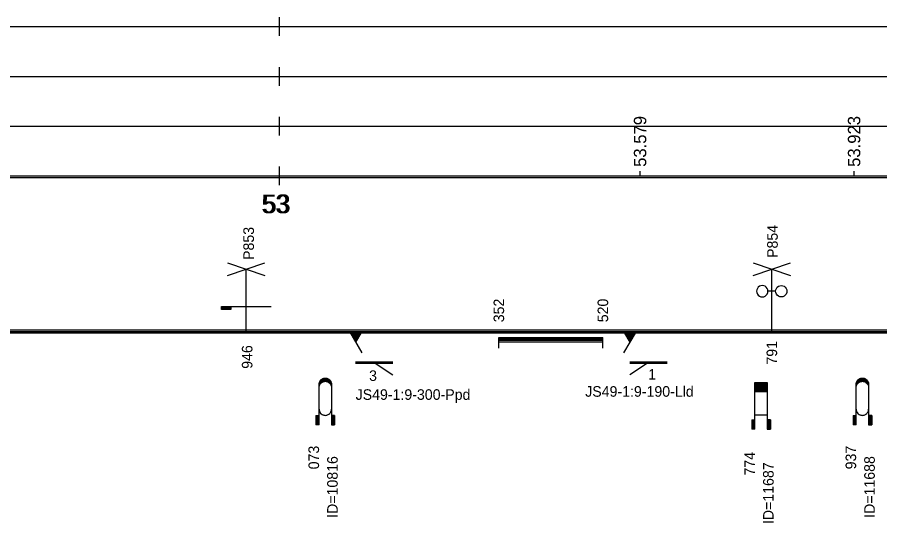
# Model space of a CAD drawing. Extents: x 2 to 10148, y 0 to 380.
# Drawn here: x 5559.3 to 5697.9, y 94.2 to 175.5 of the extents above; entities that cross this region are included whole.
import ezdxf

# ---------------------------------------------------------------- set-up
doc = ezdxf.new("R2010")
doc.units = 0
for name, color, linetype in [('CARA_S_OBJEKTY', 7, 'Continuous'), ('L_OBJEKTY_TEXT', 7, 'Continuous'), ('L_OBJEKTY_TVAR', 7, 'Continuous'), ('OBJEKTY_TEXT', 7, 'Continuous'), ('OBJEKTY_TVAR', 7, 'Continuous'), ('RYCHL_RASTR', 7, 'Continuous'), ('RYCHL_STAN', 7, 'Continuous'), ('STANIC_ZMEN_V', 7, 'Continuous')]:
    doc.layers.add(name, color=color, linetype=linetype)

msp = doc.modelspace()

# ---------------------------------------------------------------- linework, layer by layer
at = {"layer": 'CARA_S_OBJEKTY'}
for p, q in [((5128.6, 125.25), (5974.91, 125.25)), ((5128.6, 125), (5974.91, 125)), ((5128.6, 124.75), (5974.91, 124.75))]:
    msp.add_line(p, q, dxfattribs=at)
at = {"layer": 'L_OBJEKTY_TVAR'}
for p, q in [((5636.72, 124), (5653.44, 124)), ((5636.72, 122.33), (5636.72, 124)), ((5636.72, 123.83), (5653.44, 123.83)), ((5636.72, 123.58), (5653.44, 123.58)), ((5653.44, 122.33), (5653.44, 124)), ((5636.72, 123.33), (5653.44, 123.33))]:
    msp.add_line(p, q, dxfattribs=at)
at = {"layer": 'OBJEKTY_TVAR'}
for p, q in [((5593.12, 134), (5599.12, 136)), ((5593.12, 136), (5599.12, 134)), ((5677.59, 134), (5683.59, 136)), ((5677.59, 136), (5683.59, 134)), ((5596.12, 125), (5596.12, 135)), ((5680.59, 125), (5680.59, 135)), ((5678.27, 131.92), (5678.18, 131.7)), ((5678.42, 132.11), (5678.27, 131.92)), ((5678.61, 132.25), (5678.42, 132.11)), ((5678.83, 132.34), (5678.61, 132.25)), ((5679.06, 132.38), (5678.83, 132.34)), ((5679.3, 132.34), (5679.06, 132.38)), ((5679.52, 132.25), (5679.3, 132.34)), ((5679.71, 132.11), (5679.52, 132.25)), ((5679.85, 131.92), (5679.71, 132.11)), ((5679.94, 131.7), (5679.85, 131.92)), ((5681.24, 131.7), (5681.33, 131.92)), ((5681.33, 131.92), (5681.47, 132.11)), ((5681.47, 132.11), (5681.66, 132.25)), ((5681.66, 132.25), (5681.88, 132.34)), ((5681.88, 132.34), (5682.12, 132.38)), ((5682.12, 132.38), (5682.35, 132.34)), ((5682.35, 132.34), (5682.57, 132.25)), ((5682.57, 132.25), (5682.76, 132.11)), ((5682.76, 132.11), (5682.91, 131.92)), ((5682.91, 131.92), (5683, 131.7)), ((5678.18, 131.7), (5678.15, 131.46)), ((5678.15, 131.46), (5678.18, 131.23)), ((5678.18, 131.23), (5678.27, 131.01)), ((5678.27, 131.01), (5678.42, 130.82)), ((5678.42, 130.82), (5678.61, 130.67)), ((5678.61, 130.67), (5678.83, 130.58)), ((5678.83, 130.58), (5679.06, 130.55)), ((5679.06, 130.55), (5679.3, 130.58)), ((5679.3, 130.58), (5679.52, 130.67)), ((5679.52, 130.67), (5679.71, 130.82)), ((5679.71, 130.82), (5679.85, 131.01)), ((5679.85, 131.01), (5679.94, 131.23)), ((5679.97, 131.46), (5679.94, 131.7)), ((5679.94, 131.23), (5679.97, 131.46)), ((5681.21, 131.46), (5679.97, 131.46)), ((5681.21, 131.46), (5681.24, 131.7)), ((5681.24, 131.23), (5681.21, 131.46)), ((5681.33, 131.01), (5681.24, 131.23)), ((5681.47, 130.82), (5681.33, 131.01)), ((5681.66, 130.67), (5681.47, 130.82)), ((5681.88, 130.58), (5681.66, 130.67)), ((5682.12, 130.55), (5681.88, 130.58)), ((5682.35, 130.58), (5682.12, 130.55)), ((5682.57, 130.67), (5682.35, 130.58)), ((5682.76, 130.82), (5682.57, 130.67)), ((5682.91, 131.01), (5682.76, 130.82)), ((5683, 131.23), (5682.91, 131.01)), ((5683, 131.7), (5683.03, 131.46)), ((5683.03, 131.46), (5683, 131.23)), ((5592.12, 128.5), (5592.12, 129)), ((5592.12, 129), (5593.62, 129)), ((5593.62, 129), (5593.62, 128.5)), ((5593.62, 129), (5594.12, 129)), ((5594.12, 129), (5595.12, 129)), ((5595.12, 129), (5596.12, 129)), ((5596.12, 129), (5597.12, 129)), ((5597.12, 129), (5598.12, 129)), ((5598.12, 129), (5599.12, 129)), ((5599.12, 129), (5600.12, 129)), ((5593.62, 128.75), (5592.12, 128.75)), ((5593.62, 128.5), (5592.12, 128.5)), ((5612.7, 125), (5614.7, 121.54)), ((5612.9, 125), (5612.8, 124.83)), ((5613.05, 125), (5612.87, 124.7)), ((5613.2, 125), (5612.95, 124.57)), ((5613.35, 125), (5613.02, 124.44)), ((5613.5, 125), (5613.1, 124.31)), ((5613.65, 125), (5613.17, 124.18)), ((5613.8, 125), (5613.25, 124.05)), ((5613.95, 125), (5613.32, 123.92)), ((5614.1, 125), (5613.4, 123.79)), ((5614.25, 125), (5613.47, 123.66)), ((5614.4, 125), (5613.55, 123.53)), ((5614.55, 125), (5613.62, 123.4)), ((5614.7, 125), (5613.7, 123.27)), ((5656.78, 125), (5657.78, 123.27)), ((5658.78, 125), (5656.78, 121.54)), ((5656.93, 125), (5657.85, 123.4)), ((5657.08, 125), (5657.93, 123.53)), ((5657.23, 125), (5658, 123.66)), ((5657.38, 125), (5658.08, 123.79)), ((5657.53, 125), (5658.15, 123.92)), ((5657.68, 125), (5658.23, 124.05)), ((5657.83, 125), (5658.3, 124.18)), ((5657.98, 125), (5658.38, 124.31)), ((5658.13, 125), (5658.45, 124.44)), ((5658.28, 125), (5658.53, 124.57)), ((5658.43, 125), (5658.6, 124.7)), ((5658.58, 125), (5658.68, 124.83)), ((5613.7, 120.12), (5619.7, 120.12)), ((5613.7, 120), (5619.7, 120)), ((5613.7, 119.88), (5619.7, 119.88)), ((5616.7, 120), (5619.7, 118)), ((5657.78, 120.12), (5663.78, 120.12)), ((5657.78, 120), (5663.78, 120)), ((5660.78, 120), (5657.78, 118)), ((5657.78, 119.88), (5663.78, 119.88)), ((5607.82, 116.5), (5607.83, 116.65)), ((5607.82, 116.55), (5608, 116.55)), ((5607.82, 110), (5607.82, 116.5)), ((5607.82, 116.5), (5607.97, 116.5)), ((5607.83, 116.65), (5607.87, 116.81)), ((5607.83, 116.65), (5608.08, 116.65)), ((5607.83, 116.6), (5608.04, 116.6)), ((5607.84, 116.7), (5608.13, 116.7)), ((5607.85, 116.75), (5608.19, 116.75)), ((5607.87, 116.81), (5607.93, 116.95)), ((5607.87, 116.8), (5608.25, 116.8)), ((5607.88, 116.85), (5608.33, 116.85)), ((5607.9, 116.9), (5608.44, 116.9)), ((5607.93, 116.95), (5607.99, 117.06)), ((5607.93, 116.95), (5608.59, 116.95)), ((5607.93, 116.43), (5607.99, 116.53)), ((5607.95, 117), (5609.69, 117)), ((5607.98, 117.05), (5609.66, 117.05)), ((5607.99, 117.06), (5608.08, 117.18)), ((5607.99, 116.53), (5608.08, 116.65)), ((5608.02, 117.1), (5609.62, 117.1)), ((5608.06, 117.15), (5609.58, 117.15)), ((5608.08, 117.18), (5608.17, 117.26)), ((5608.08, 116.65), (5608.17, 116.74)), ((5608.11, 117.2), (5609.53, 117.2)), ((5608.16, 117.25), (5609.48, 117.25)), ((5608.17, 117.26), (5608.3, 117.35)), ((5608.17, 116.74), (5608.3, 116.83)), ((5608.22, 117.3), (5609.42, 117.3)), ((5608.29, 117.35), (5609.35, 117.35)), ((5608.3, 117.35), (5608.43, 117.42)), ((5608.3, 116.83), (5608.43, 116.9)), ((5608.38, 117.4), (5609.26, 117.4)), ((5608.43, 117.42), (5608.46, 117.43)), ((5608.43, 116.9), (5608.46, 116.91)), ((5608.46, 117.43), (5608.58, 117.47)), ((5608.46, 116.91), (5608.58, 116.95)), ((5608.51, 117.45), (5609.13, 117.45)), ((5608.58, 117.47), (5608.72, 117.49)), ((5608.58, 116.95), (5608.72, 116.97)), ((5608.72, 117.49), (5608.83, 117.5)), ((5608.72, 116.97), (5608.83, 116.98)), ((5608.83, 117.5), (5608.96, 117.49)), ((5608.83, 116.98), (5608.96, 116.97)), ((5608.96, 117.49), (5609.09, 117.46)), ((5608.96, 116.97), (5609.09, 116.94)), ((5609.05, 116.95), (5609.71, 116.95)), ((5609.09, 117.46), (5609.2, 117.43)), ((5609.09, 116.94), (5609.2, 116.9)), ((5609.2, 117.43), (5609.31, 117.37)), ((5609.2, 116.9), (5609.31, 116.85)), ((5609.2, 116.9), (5609.74, 116.9)), ((5609.31, 117.37), (5609.38, 117.32)), ((5609.31, 116.85), (5609.76, 116.85)), ((5609.31, 116.85), (5609.38, 116.8)), ((5609.38, 117.32), (5609.53, 117.21)), ((5609.38, 116.8), (5609.53, 116.68)), ((5609.39, 116.8), (5609.77, 116.8)), ((5609.45, 116.75), (5609.79, 116.75)), ((5609.51, 116.7), (5609.8, 116.7)), ((5609.53, 117.21), (5609.61, 117.11)), ((5609.53, 116.68), (5609.61, 116.59)), ((5609.56, 116.65), (5609.81, 116.65)), ((5609.6, 116.6), (5609.81, 116.6)), ((5609.61, 117.11), (5609.7, 116.98)), ((5609.61, 116.59), (5609.7, 116.46)), ((5609.64, 116.55), (5609.82, 116.55)), ((5609.67, 116.5), (5609.82, 116.5)), ((5609.7, 116.98), (5609.74, 116.89)), ((5609.7, 116.46), (5609.74, 116.37)), ((5609.74, 116.89), (5609.78, 116.77)), ((5609.78, 116.77), (5609.81, 116.65)), ((5609.81, 116.65), (5609.82, 116.56)), ((5609.82, 116.56), (5609.82, 116.5)), ((5609.82, 116.5), (5609.82, 110)), ((5677.87, 109.28), (5677.87, 116.78)), ((5677.87, 116.78), (5679.87, 116.78)), ((5677.87, 116.73), (5679.87, 116.73)), ((5677.87, 116.68), (5679.87, 116.68)), ((5677.87, 116.63), (5679.87, 116.63)), ((5677.87, 116.58), (5679.87, 116.58)), ((5677.87, 116.53), (5679.87, 116.53)), ((5677.87, 116.48), (5679.87, 116.48)), ((5679.87, 116.78), (5679.87, 109.28)), ((5694.15, 116.5), (5694.16, 116.65)), ((5694.15, 116.55), (5694.33, 116.55)), ((5694.15, 110), (5694.15, 116.5)), ((5694.15, 116.5), (5694.3, 116.5)), ((5694.16, 116.65), (5694.2, 116.81)), ((5694.16, 116.65), (5694.41, 116.65)), ((5694.16, 116.6), (5694.37, 116.6)), ((5694.17, 116.7), (5694.46, 116.7)), ((5694.18, 116.75), (5694.52, 116.75)), ((5694.2, 116.81), (5694.26, 116.95)), ((5694.2, 116.8), (5694.58, 116.8)), ((5694.21, 116.85), (5694.66, 116.85)), ((5694.23, 116.9), (5694.77, 116.9)), ((5694.26, 116.95), (5694.32, 117.06)), ((5694.26, 116.95), (5694.92, 116.95)), ((5694.26, 116.43), (5694.32, 116.53)), ((5694.28, 117), (5696.02, 117)), ((5694.31, 117.05), (5695.99, 117.05)), ((5694.32, 117.06), (5694.41, 117.18)), ((5694.32, 116.53), (5694.41, 116.65)), ((5694.35, 117.1), (5695.95, 117.1)), ((5694.39, 117.15), (5695.91, 117.15)), ((5694.41, 117.18), (5694.5, 117.26)), ((5694.41, 116.65), (5694.5, 116.74)), ((5694.44, 117.2), (5695.86, 117.2)), ((5694.49, 117.25), (5695.81, 117.25)), ((5694.5, 117.26), (5694.63, 117.35)), ((5694.5, 116.74), (5694.63, 116.83)), ((5694.55, 117.3), (5695.75, 117.3)), ((5694.62, 117.35), (5695.68, 117.35)), ((5694.63, 117.35), (5694.76, 117.42)), ((5694.63, 116.83), (5694.76, 116.9)), ((5694.71, 117.4), (5695.59, 117.4)), ((5694.76, 117.42), (5694.79, 117.43)), ((5694.76, 116.9), (5694.79, 116.91)), ((5694.79, 117.43), (5694.91, 117.47)), ((5694.79, 116.91), (5694.91, 116.95)), ((5694.84, 117.45), (5695.46, 117.45)), ((5694.91, 117.47), (5695.05, 117.49)), ((5694.91, 116.95), (5695.05, 116.97)), ((5695.05, 117.49), (5695.16, 117.5)), ((5695.05, 116.97), (5695.16, 116.98)), ((5695.16, 117.5), (5695.29, 117.49)), ((5695.16, 116.98), (5695.29, 116.97)), ((5695.29, 117.49), (5695.42, 117.46)), ((5695.29, 116.97), (5695.42, 116.94)), ((5695.38, 116.95), (5696.04, 116.95)), ((5695.42, 117.46), (5695.53, 117.43)), ((5695.42, 116.94), (5695.53, 116.9)), ((5695.53, 117.43), (5695.64, 117.37)), ((5695.53, 116.9), (5695.64, 116.85)), ((5695.53, 116.9), (5696.07, 116.9)), ((5695.64, 117.37), (5695.71, 117.32)), ((5695.64, 116.85), (5696.09, 116.85)), ((5695.64, 116.85), (5695.71, 116.8)), ((5695.71, 117.32), (5695.86, 117.21)), ((5695.71, 116.8), (5695.86, 116.68)), ((5695.72, 116.8), (5696.1, 116.8)), ((5695.78, 116.75), (5696.12, 116.75)), ((5695.84, 116.7), (5696.13, 116.7)), ((5695.86, 117.21), (5695.94, 117.11)), ((5695.86, 116.68), (5695.94, 116.59)), ((5695.89, 116.65), (5696.14, 116.65)), ((5695.93, 116.6), (5696.14, 116.6)), ((5695.94, 117.11), (5696.03, 116.98)), ((5695.94, 116.59), (5696.03, 116.46)), ((5695.97, 116.55), (5696.15, 116.55)), ((5696, 116.5), (5696.15, 116.5)), ((5696.03, 116.98), (5696.07, 116.89)), ((5696.03, 116.46), (5696.07, 116.37)), ((5696.07, 116.89), (5696.11, 116.77)), ((5696.11, 116.77), (5696.14, 116.65)), ((5696.14, 116.65), (5696.15, 116.56)), ((5696.15, 116.56), (5696.15, 116.5)), ((5696.15, 116.5), (5696.15, 110)), ((5607.82, 116.45), (5607.94, 116.45)), ((5607.82, 116.4), (5607.91, 116.4)), ((5607.82, 116.35), (5607.89, 116.35)), ((5607.82, 116.3), (5607.87, 116.3)), ((5607.82, 116.25), (5607.86, 116.25)), ((5607.82, 116.2), (5607.85, 116.2)), ((5607.82, 116.15), (5607.84, 116.15)), ((5607.82, 115.98), (5607.83, 116.13)), ((5607.82, 116.1), (5607.83, 116.1)), ((5607.83, 116.13), (5607.87, 116.28)), ((5607.87, 116.28), (5607.93, 116.43)), ((5609.7, 116.45), (5609.82, 116.45)), ((5609.73, 116.4), (5609.82, 116.4)), ((5609.74, 116.37), (5609.78, 116.24)), ((5609.75, 116.35), (5609.82, 116.35)), ((5609.77, 116.3), (5609.82, 116.3)), ((5609.78, 116.25), (5609.82, 116.25)), ((5609.78, 116.24), (5609.81, 116.13)), ((5609.79, 116.2), (5609.82, 116.2)), ((5609.8, 116.15), (5609.82, 116.15)), ((5609.81, 116.13), (5609.82, 116.03)), ((5609.81, 116.1), (5609.82, 116.1)), ((5609.82, 116.03), (5609.82, 115.98)), ((5677.87, 116.43), (5679.87, 116.43)), ((5677.87, 116.38), (5679.87, 116.38)), ((5677.87, 116.33), (5679.87, 116.33)), ((5677.87, 116.28), (5679.87, 116.28)), ((5677.87, 116.23), (5679.87, 116.23)), ((5677.87, 116.18), (5679.87, 116.18)), ((5677.87, 116.13), (5679.87, 116.13)), ((5677.87, 116.08), (5679.87, 116.08)), ((5677.87, 116.03), (5679.87, 116.03)), ((5677.87, 115.98), (5679.87, 115.98)), ((5677.87, 115.93), (5679.87, 115.93)), ((5677.87, 115.88), (5679.87, 115.88)), ((5677.87, 115.83), (5679.87, 115.83)), ((5677.87, 115.78), (5679.87, 115.78)), ((5677.87, 115.73), (5679.87, 115.73)), ((5677.87, 115.68), (5679.87, 115.68)), ((5677.87, 115.63), (5679.87, 115.63)), ((5677.87, 115.58), (5679.87, 115.58)), ((5677.87, 115.53), (5679.87, 115.53)), ((5677.87, 115.48), (5679.87, 115.48)), ((5677.87, 115.43), (5679.87, 115.43)), ((5677.87, 115.38), (5679.87, 115.38)), ((5677.87, 115.33), (5679.87, 115.33)), ((5694.15, 116.45), (5694.27, 116.45)), ((5694.15, 116.4), (5694.24, 116.4)), ((5694.15, 116.35), (5694.22, 116.35)), ((5694.15, 116.3), (5694.2, 116.3)), ((5694.15, 116.25), (5694.19, 116.25)), ((5694.15, 116.2), (5694.18, 116.2)), ((5694.15, 116.15), (5694.17, 116.15)), ((5694.15, 115.98), (5694.16, 116.13)), ((5694.15, 116.1), (5694.16, 116.1)), ((5694.16, 116.13), (5694.2, 116.28)), ((5694.2, 116.28), (5694.26, 116.43)), ((5696.03, 116.45), (5696.15, 116.45)), ((5696.06, 116.4), (5696.15, 116.4)), ((5696.07, 116.37), (5696.11, 116.24)), ((5696.08, 116.35), (5696.15, 116.35)), ((5696.1, 116.3), (5696.15, 116.3)), ((5696.11, 116.25), (5696.15, 116.25)), ((5696.11, 116.24), (5696.14, 116.13)), ((5696.12, 116.2), (5696.15, 116.2)), ((5696.13, 116.15), (5696.15, 116.15)), ((5696.14, 116.13), (5696.15, 116.03)), ((5696.14, 116.1), (5696.15, 116.1)), ((5696.15, 116.03), (5696.15, 115.98)), ((5607.82, 112.5), (5607.83, 112.35)), ((5607.83, 112.35), (5607.87, 112.2)), ((5609.78, 112.24), (5609.81, 112.35)), ((5609.81, 112.35), (5609.82, 112.45)), ((5609.82, 112.45), (5609.82, 112.5)), ((5694.15, 112.5), (5694.16, 112.35)), ((5694.16, 112.35), (5694.2, 112.2)), ((5696.11, 112.24), (5696.14, 112.35)), ((5696.14, 112.35), (5696.15, 112.45)), ((5696.15, 112.45), (5696.15, 112.5)), ((5607.32, 111.5), (5607.82, 111.5)), ((5607.32, 111.5), (5607.32, 110)), ((5607.37, 111.5), (5607.37, 110)), ((5607.42, 111.5), (5607.42, 110)), ((5607.47, 111.5), (5607.47, 110)), ((5607.52, 111.5), (5607.52, 110)), ((5607.57, 111.5), (5607.57, 110)), ((5607.62, 111.5), (5607.62, 110)), ((5607.67, 111.5), (5607.67, 110)), ((5607.72, 111.5), (5607.72, 110)), ((5607.77, 111.5), (5607.77, 110)), ((5607.87, 112.2), (5607.93, 112.05)), ((5607.93, 112.05), (5607.99, 111.95)), ((5607.99, 111.95), (5608.08, 111.83)), ((5608.08, 111.83), (5608.17, 111.74)), ((5608.17, 111.74), (5608.3, 111.65)), ((5608.3, 111.65), (5608.43, 111.58)), ((5608.43, 111.58), (5608.46, 111.57)), ((5608.46, 111.57), (5608.58, 111.53)), ((5608.58, 111.53), (5608.72, 111.51)), ((5608.72, 111.51), (5608.83, 111.5)), ((5608.83, 111.5), (5608.96, 111.51)), ((5608.96, 111.51), (5609.09, 111.54)), ((5609.09, 111.54), (5609.2, 111.58)), ((5609.2, 111.58), (5609.31, 111.63)), ((5609.31, 111.63), (5609.38, 111.68)), ((5609.38, 111.68), (5609.53, 111.8)), ((5609.53, 111.8), (5609.61, 111.9)), ((5609.61, 111.9), (5609.7, 112.02)), ((5609.7, 112.02), (5609.74, 112.11)), ((5609.74, 112.11), (5609.78, 112.24)), ((5610.32, 111.5), (5609.82, 111.5)), ((5609.87, 111.5), (5609.87, 110)), ((5609.92, 111.5), (5609.92, 110)), ((5609.97, 111.5), (5609.97, 110)), ((5610.02, 111.5), (5610.02, 110)), ((5610.07, 111.5), (5610.07, 110)), ((5610.12, 111.5), (5610.12, 110)), ((5610.17, 111.5), (5610.17, 110)), ((5610.22, 111.5), (5610.22, 110)), ((5610.27, 111.5), (5610.27, 110)), ((5610.32, 111.5), (5610.32, 110)), ((5677.87, 111.59), (5679.87, 111.59)), ((5693.65, 111.5), (5694.15, 111.5)), ((5693.65, 111.5), (5693.65, 110)), ((5693.7, 111.5), (5693.7, 110)), ((5693.75, 111.5), (5693.75, 110)), ((5693.8, 111.5), (5693.8, 110)), ((5693.85, 111.5), (5693.85, 110)), ((5693.9, 111.5), (5693.9, 110)), ((5693.95, 111.5), (5693.95, 110)), ((5694, 111.5), (5694, 110)), ((5694.05, 111.5), (5694.05, 110)), ((5694.1, 111.5), (5694.1, 110)), ((5694.2, 112.2), (5694.26, 112.05)), ((5694.26, 112.05), (5694.32, 111.95)), ((5694.32, 111.95), (5694.41, 111.83)), ((5694.41, 111.83), (5694.5, 111.74)), ((5694.5, 111.74), (5694.63, 111.65)), ((5694.63, 111.65), (5694.76, 111.58)), ((5694.76, 111.58), (5694.79, 111.57)), ((5694.79, 111.57), (5694.91, 111.53)), ((5694.91, 111.53), (5695.05, 111.51)), ((5695.05, 111.51), (5695.16, 111.5)), ((5695.16, 111.5), (5695.29, 111.51)), ((5695.29, 111.51), (5695.42, 111.54)), ((5695.42, 111.54), (5695.53, 111.58)), ((5695.53, 111.58), (5695.64, 111.63)), ((5695.64, 111.63), (5695.71, 111.68)), ((5695.71, 111.68), (5695.86, 111.8)), ((5695.86, 111.8), (5695.94, 111.9)), ((5695.94, 111.9), (5696.03, 112.02)), ((5696.03, 112.02), (5696.07, 112.11)), ((5696.07, 112.11), (5696.11, 112.24)), ((5696.65, 111.5), (5696.15, 111.5)), ((5696.2, 111.5), (5696.2, 110)), ((5696.25, 111.5), (5696.25, 110)), ((5696.3, 111.5), (5696.3, 110)), ((5696.35, 111.5), (5696.35, 110)), ((5696.4, 111.5), (5696.4, 110)), ((5696.45, 111.5), (5696.45, 110)), ((5696.5, 111.5), (5696.5, 110)), ((5696.55, 111.5), (5696.55, 110)), ((5696.6, 111.5), (5696.6, 110)), ((5696.65, 111.5), (5696.65, 110)), ((5607.82, 110), (5607.32, 110)), ((5609.82, 110), (5610.32, 110)), ((5677.37, 110.78), (5677.87, 110.78)), ((5677.37, 110.78), (5677.37, 109.28)), ((5677.42, 110.78), (5677.42, 109.28)), ((5677.47, 110.78), (5677.47, 109.28)), ((5677.52, 110.78), (5677.52, 109.28)), ((5677.57, 110.78), (5677.57, 109.28)), ((5677.62, 110.78), (5677.62, 109.28)), ((5677.67, 110.78), (5677.67, 109.28)), ((5677.72, 110.78), (5677.72, 109.28)), ((5677.77, 110.78), (5677.77, 109.28)), ((5677.82, 110.78), (5677.82, 109.28)), ((5680.37, 110.78), (5679.87, 110.78)), ((5679.92, 110.78), (5679.92, 109.28)), ((5679.97, 110.78), (5679.97, 109.28)), ((5680.02, 110.78), (5680.02, 109.28)), ((5680.07, 110.78), (5680.07, 109.28)), ((5680.12, 110.78), (5680.12, 109.28)), ((5680.17, 110.78), (5680.17, 109.28)), ((5680.22, 110.78), (5680.22, 109.28)), ((5680.27, 110.78), (5680.27, 109.28)), ((5680.32, 110.78), (5680.32, 109.28)), ((5680.37, 110.78), (5680.37, 109.28)), ((5694.15, 110), (5693.65, 110)), ((5696.15, 110), (5696.65, 110)), ((5677.87, 109.28), (5677.37, 109.28)), ((5679.87, 109.28), (5680.37, 109.28))]:
    msp.add_line(p, q, dxfattribs=at)
at = {"layer": 'RYCHL_RASTR'}
for p, q in [((5601.49, 172.5), (5601.49, 175.5)), ((5122.71, 174), (5974.23, 174)), ((5601.49, 164.5), (5601.49, 167.5)), ((5122.69, 166), (5974.36, 166)), ((5601.49, 156.5), (5601.49, 159.5)), ((5122.67, 158), (5974.55, 158)), ((5601.49, 148.5), (5601.49, 151.5)), ((5128.6, 150), (5974.91, 150)), ((5128.6, 149.75), (5974.91, 149.75))]:
    msp.add_line(p, q, dxfattribs=at)
at = {"layer": 'STANIC_ZMEN_V'}
for p, q in [((5659.42, 150), (5659.42, 150.75)), ((5693.82, 150), (5693.82, 150.75))]:
    msp.add_line(p, q, dxfattribs=at)

# ---------------------------------------------------------------- texts
at = {"layer": 'L_OBJEKTY_TEXT'}
for s, p in [('352', (5637.57, 126.47)), ('520', (5654.29, 126.47))]:
    msp.add_text(s, height=1.7, rotation=90, dxfattribs=at).set_placement(p)
at = {"layer": 'OBJEKTY_TEXT'}
for s, p in [('P853', (5597.35, 136.49)), ('P854', (5681.55, 136.81)), ('946', (5597.11, 118.99)), ('791', (5681.45, 119.66)), ('073', (5607.82, 102.83)), ('774', (5677.89, 101.83)), ('937', (5694.15, 102.83)), ('ID=10816', (5610.82, 95.03)), ('ID=11688', (5697.15, 95.03)), ('ID=11687', (5680.89, 94.03))]:
    msp.add_text(s, height=1.7, rotation=90, dxfattribs=at).set_placement(p)
for s, p in [('3', (5615.86, 117.04)), ('1', (5660.72, 117.25)), ('JS49-1:9-300-Ppd', (5613.7, 114)), ('JS49-1:9-190-Lld', (5650.6, 114.5))]:
    msp.add_text(s, height=1.7, dxfattribs=at).set_placement(p)
at = {"layer": 'RYCHL_STAN'}
for p in [(5598.55, 144), (5598.8, 144)]:
    msp.add_text('53', height=3, dxfattribs=at).set_placement(p)
at = {"layer": 'STANIC_ZMEN_V'}
for s, p in [('53.579', (5660.42, 151.45)), ('53.923', (5694.82, 151.45))]:
    msp.add_text(s, height=2, rotation=90, dxfattribs=at).set_placement(p)

doc.saveas('drawing.dxf')
